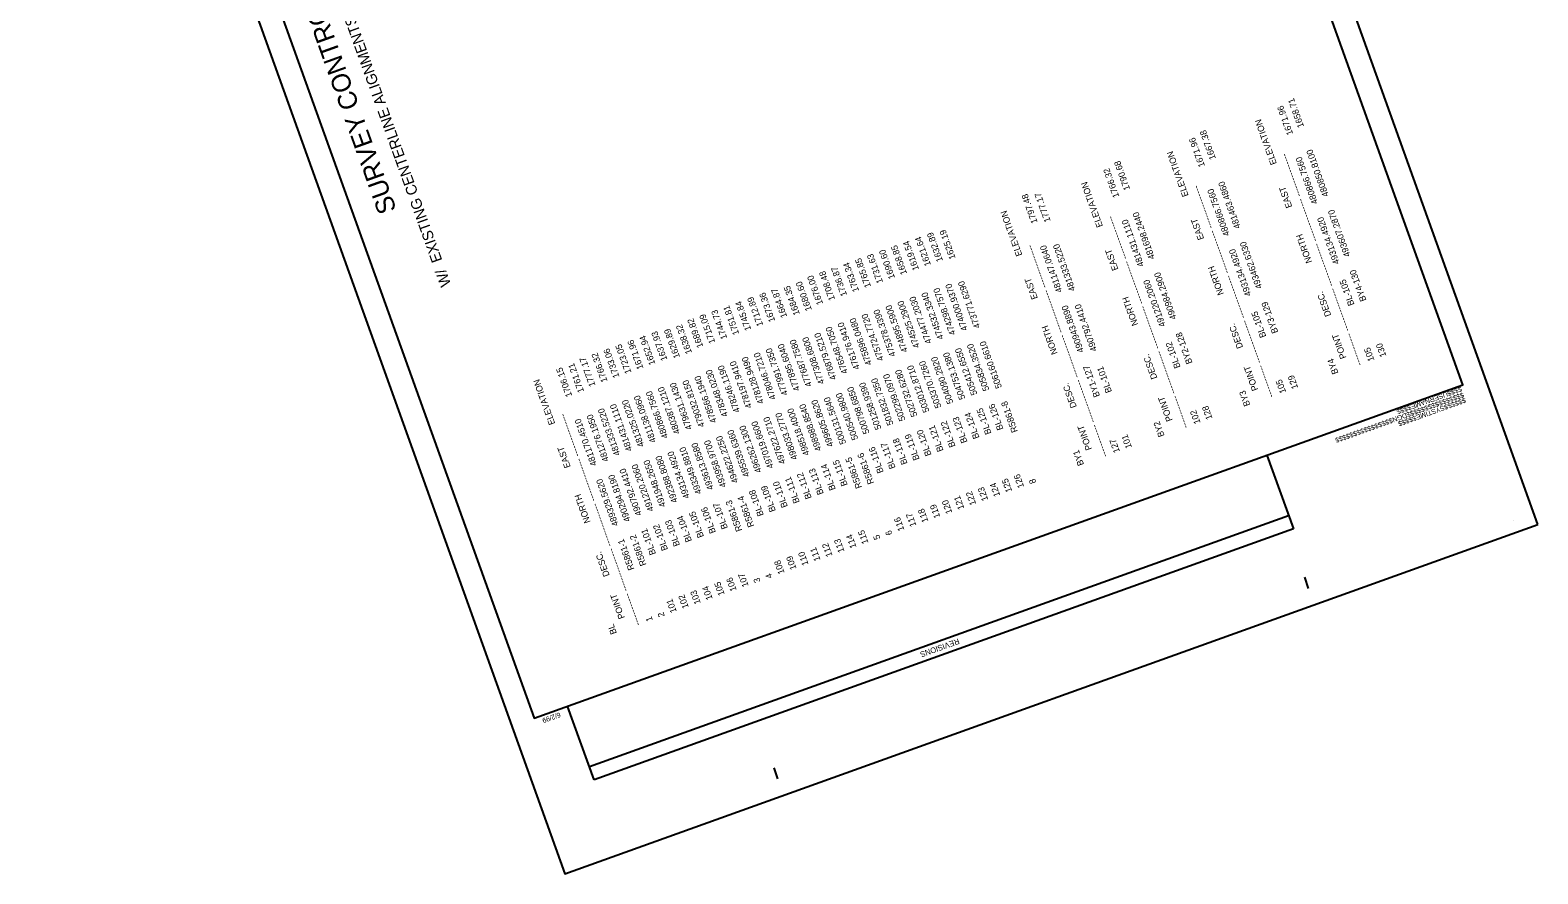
# Model space of a CAD drawing. Extents: x 473103 to 476656, y 504228 to 508561.
# Drawn here: x 473103 to 476656, y 504228 to 506216 of the extents above; entities that cross this region are included whole.
import ezdxf

# ---------------------------------------------------------------- set-up
doc = ezdxf.new("R2010")
doc.units = 0
for name, color, linetype in [('CTL Sheet Border CELL', 7, 'Continuous'), ('CTL Sheet Text', 7, 'Continuous'), ('Sheet Block Revision CELL', 7, 'Continuous'), ('Sheet Plot Border Outside CELL', 7, 'Continuous')]:
    doc.layers.add(name, color=color, linetype=linetype)

msp = doc.modelspace()

# ---------------------------------------------------------------- linework, layer by layer
at = {"layer": 'CTL Sheet Border CELL'}
for p, q in [((476479.2, 505380.1), (476479.2, 505380.1)), ((476479.2, 505380.1), (476479.2, 505380.1)), ((476479.2, 505380.1), (476479.2, 505380.1)), ((476479.2, 505380.1), (476479.2, 505380.1)), ((476479.2, 505380.1), (476479.2, 505380.1)), ((476479.2, 505380.1), (476479.2, 505380.1)), ((476479.2, 505380.1), (476479.2, 505380.1)), ((476479.2, 505380.1), (476479.2, 505380.1)), ((476479.2, 505380.1), (476479.2, 505380.1)), ((476479.2, 505380.1), (476479.2, 505380.1)), ((476479.2, 505380.1), (476479.2, 505380.1)), ((476599.8, 505061), (476599.8, 505061)), ((476656.3, 505050.7), (476656.3, 505050.7)), ((476116.2, 504900.3), (476106.8, 504926.4)), ((474865.5, 504451.3), (474856.2, 504477.3))]:
    msp.add_line(p, q, dxfattribs=at)
msp.add_lwpolyline([(473168, 507720.9), (474290.6, 504594.3), (476479.2, 505380.1), (475356.6, 508506.7)], close=True, dxfattribs=at)
msp.add_lwpolyline([(476451.2, 505458.3), (476451.2, 505458.3)], dxfattribs=at)
msp.add_lwpolyline([(476451.2, 505458.3), (476451.2, 505458.3)], dxfattribs=at)
at = {"layer": 'Sheet Block Revision CELL'}
for p, q in [((476017.5, 505214.3), (476080.1, 505040.3)), ((476068.8, 505071.5), (474421.3, 504480)), ((476080.1, 505040.3), (474432.5, 504448.7)), ((474432.5, 504448.7), (474369.9, 504622.8))]:
    msp.add_line(p, q, dxfattribs=at)
at = {"layer": 'Sheet Plot Border Outside CELL'}
msp.add_lwpolyline([(476656.3, 505050.7), (475396, 508560.9), (473103.2, 507737.6), (474363.5, 504227.5)], close=True, dxfattribs=at)

# ---------------------------------------------------------------- texts
at = {"layer": 'CTL Sheet Border CELL'}
for s, height, rotation, p in [('W/  EXISTING CENTERLINE ALIGNMENTS PRIOR TO CONSTRUCTION', 25.469, 109.7508, (474095.3, 505616.4)), ('SURVEY CONTROL SHEET ', 44.294, 109.7508, (473967.3, 505792.2)), ('$$$$$$$$$$$$$$$$DGN$$$$$$$$$$$$$$$$', 11.627, 199.7508, (476480, 505362.4)), ('$$$$USERNAME$$$$', 11.627, 199.7508, (476475.1, 505376.1)), ('$$$$$$SYSTIME$$$$$', 11.627, 199.7508, (476484.5, 505349.8)), ('6/2/99', 11.63, 199.7508, (474350.8, 504608.5))]:
    msp.add_text(s, height=height, rotation=rotation, dxfattribs=at).set_placement(p)
at = {"layer": 'CTL Sheet Text'}
for s, p in [('105                   BL-105       493134.4920      480866.7560          1671.96', (476271.4, 505438.1)), ('130                   BY4-130      493607.2870      480850.8100          1658.71', (476299.6, 505448.2)), ('     POINT        DESC.             NORTH            EAST          ELEVATION', (476214.9, 505417.8)), ('129                   BY3-129      493462.6330      481463.4860          1667.38', (476091.8, 505372.9)), ('     POINT        DESC.             NORTH            EAST          ELEVATION', (476007.1, 505342.5)), ('105                   BL-105       493134.4920      480866.7560          1671.96', (476063.5, 505362.8)), ('128                   BY2-128      490984.2900      481698.2440          1790.68', (475889.8, 505300.7)), ('------------ ---------------- ---------------- ---------------- ----------------', (476243.1, 505427.9)), ('     POINT        DESC.             NORTH            EAST          ELEVATION', (475805.1, 505270.3)), ('102                   BL-102       491220.2060      481431.1110          1766.32', (475861.6, 505290.6)), ('127                   BY1-127      490943.8890      481147.0640          1797.48', (475671.7, 505222.6)), ('101                   BL-101       490792.4410      481333.5220          1777.17', (475699.9, 505232.8)), ('------------ ---------------- ---------------- ---------------- ----------------', (476035.3, 505352.6)), ('     POINT        DESC.             NORTH            EAST          ELEVATION', (475615.2, 505202.4)), ('------------ ---------------- ---------------- ---------------- ----------------', (475833.4, 505280.4)), ('124                    BL-124      504753.1380      474532.3340          1619.54', (475389.6, 505119.2)), ('125                    BL-125      505412.6550      474298.7570          1621.64', (475417.8, 505129.4)), ('126                    BL-126      505834.3520      474000.9370          1632.89', (475446, 505139.5)), ('8                     R5861-8      506160.6610      473771.6290          1625.19', (475474.3, 505149.7)), ('121                    BL-121      503012.8710      474895.5900          1731.63', (475304.9, 505088.8)), ('122                    BL-122      503370.7260      474525.2900          1690.60', (475333.1, 505099)), ('123                    BL-123      504090.2820      474477.2030          1658.85', (475361.3, 505109.1)), ('------------ ---------------- ---------------- ---------------- ----------------', (475643.5, 505212.5)), ('117                    BL-117      501258.9390      476176.9410          1708.48', (475191.9, 505048.3)), ('118                    BL-118      501832.7350      475896.0480          1736.87', (475220.2, 505058.4)), ('119                    BL-119      502299.0970      475724.7720          1763.34', (475248.4, 505068.5)), ('120                    BL-120      502732.6280      475378.3390          1765.85', (475276.6, 505078.7)), ('5                     R5861-5      500131.5640      477308.6800          1684.35', (475107.2, 505017.9)), ('6                     R5861-6      500540.9800      476879.5210          1680.60', (475135.5, 505028)), ('116                    BL-116      500798.6850      476548.7050          1676.00', (475163.7, 505038.1)), ('112                    BL-112      498033.2770      478046.7210          1745.84', (474994.3, 504977.3)), ('113                    BL-113      498518.4000      477991.7350          1712.89', (475022.5, 504987.4)), ('114                    BL-114      498988.8540      477895.6040          1673.36', (475050.8, 504997.6)), ('115                    BL-115      499605.8620      477687.7580          1664.87', (475079, 505007.7)), ('109                    BL-109      496262.1300      478246.1190          1715.09', (474909.6, 504946.9)), ('110                    BL-110      497019.6600      478197.9410          1744.73', (474937.8, 504957)), ('111                    BL-111      497622.2710      478128.9490          1751.81', (474966, 504967.2)), ('107                    BL-107      493613.8580      479631.1430          1637.93', (474796.6, 504906.3)), ('3                     R5861-3      493958.9700      479032.8150          1629.89', (474824.9, 504916.5)), ('4                     R5861-4      494622.2250      478566.1940          1638.32', (474853.1, 504926.6)), ('108                    BL-108      495539.6360      478348.0230          1689.82', (474881.3, 504936.8)), ('104                    BL-104      492388.8080      481138.0960          1723.05', (474711.9, 504875.9)), ('105                    BL-105      493134.4920      480866.7560          1671.96', (474740.2, 504886.1)), ('106                    BL-106      493349.8810      480387.1210          1652.94', (474768.4, 504896.2)), ('2                     R5861-2      490294.8190      481276.1950          1761.21', (474599, 504835.4)), ('101                    BL-101      490792.4410      481333.5220          1777.17', (474627.2, 504845.5)), ('102                    BL-102      491220.2060      481431.1110          1766.32', (474655.5, 504855.7)), ('103                    BL-103      491948.2650      481325.0220          1733.06', (474683.7, 504865.8)), ('BY4', (476186.6, 505407.7)), ('1                     R5861-1      489329.5620      481170.4510          1706.15', (474570.8, 504825.2)), ('     POINT        DESC.             NORTH            EAST          ELEVATION', (474514.3, 504805)), ('BY3', (475978.8, 505332.3)), ('------------ ---------------- ---------------- ---------------- ----------------', (474542.5, 504815.1)), ('BY2', (475776.9, 505260.1)), ('BY1', (475587, 505192.2)), ('BL', (474486, 504794.8))]:
    msp.add_text(s, height=15, rotation=109.7508, dxfattribs=at).set_placement(p)
at = {"layer": 'Sheet Block Revision CELL'}
msp.add_text('REVISIONS', height=13.28, rotation=199.7508, dxfattribs=at).set_placement((475290.3, 504782.7))

doc.saveas('drawing.dxf')
